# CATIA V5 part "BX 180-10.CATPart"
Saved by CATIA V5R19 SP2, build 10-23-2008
Part number: BX 180-10
Bounding box of the stored display mesh (mm): x -24.865 to 24.865, y -24.997 to 24.997, z 0 to 80
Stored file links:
  C:\Users\Bora\Desktop\3D Katı model\BX serisi\BX 180\BX 180-10.CATPart
  C:\Program Files\Dassault Systemes\B19\intel_a\reffiles\standard\MetricThickPitch.txt
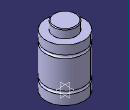
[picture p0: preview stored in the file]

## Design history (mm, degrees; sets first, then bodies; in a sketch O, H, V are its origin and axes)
Body1 (main body)
  Sketch1 on yz-plane, origin (0, 0, 0), H (0, 1, 0), V (0, 0, 1)
    point P1 (25, 12.5)
    point P2 (25, 16.5)
    arc A1 centre (25, 14.5) radius 2 from (25, 16.5) to (25, 12.5) ccw
    point P3 (25, 53.5)
    point P4 (25, 57.5)
    arc A2 centre (25, 55.5) radius 2 from (25, 57.5) to (25, 53.5) ccw
    point P5 (25, 57.5)
    line L1 (25, 69) -> (25, 57.5)
    point P8 (15, 79)
    line L2 (15, 79) -> (15, 69)
    point P10 (15, 79)
    arc A3 centre (14, 79) radius 1 from (15, 79) to (14, 80) ccw
    point P11 (25, 16.5)
    point P12 (25, 53.5)
    line L3 (25, 53.5) -> (25, 16.5)
    point P14 (25, 12.5)
    line L4 (25, 12.5) -> (25, 0)
    line L5 (14, 80) -> (0, 80)
    line L6 (15, 69) -> (25, 69)
    line L7 (25, 0) -> (0, 0)
    tangency: L5 A3
    horizontal: L6 H, L7 H
    coincidence: P1 P14, P2 P11, P3 P12, P4 P5, P8 P10
  Shaft1: profile Sketch1, axis Sketch1.V, angle 360
  Sketch2 on face of Shaft1 from Sketch1.L7, origin (0, 0, 0), H (1, 0, 0), V (0, -1, 0)
    point P1 (12.5, 0)
    distance P1 V = 12.5
  Hole1: placed by Sketch2, at (12.5, 0, 0) direction (0, 0, 1), diameter 4.917, depth 6, threaded "M6", thread diameter 6, thread depth 6, pitch 1
  Sketch3 on face of Shaft1 from Sketch1.L7, origin (0, 0, 0), H (1, 0, 0), V (0, -1, 0)
    point P1 (-12.5, 0)
    distance P1 V = 12.5
  Hole2: placed by Sketch3, at (-12.5, 0, 0) direction (0, 0, 1), diameter 4.917, depth 6, threaded "M6", thread diameter 6, thread depth 6, pitch 1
